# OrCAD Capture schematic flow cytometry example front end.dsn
size B
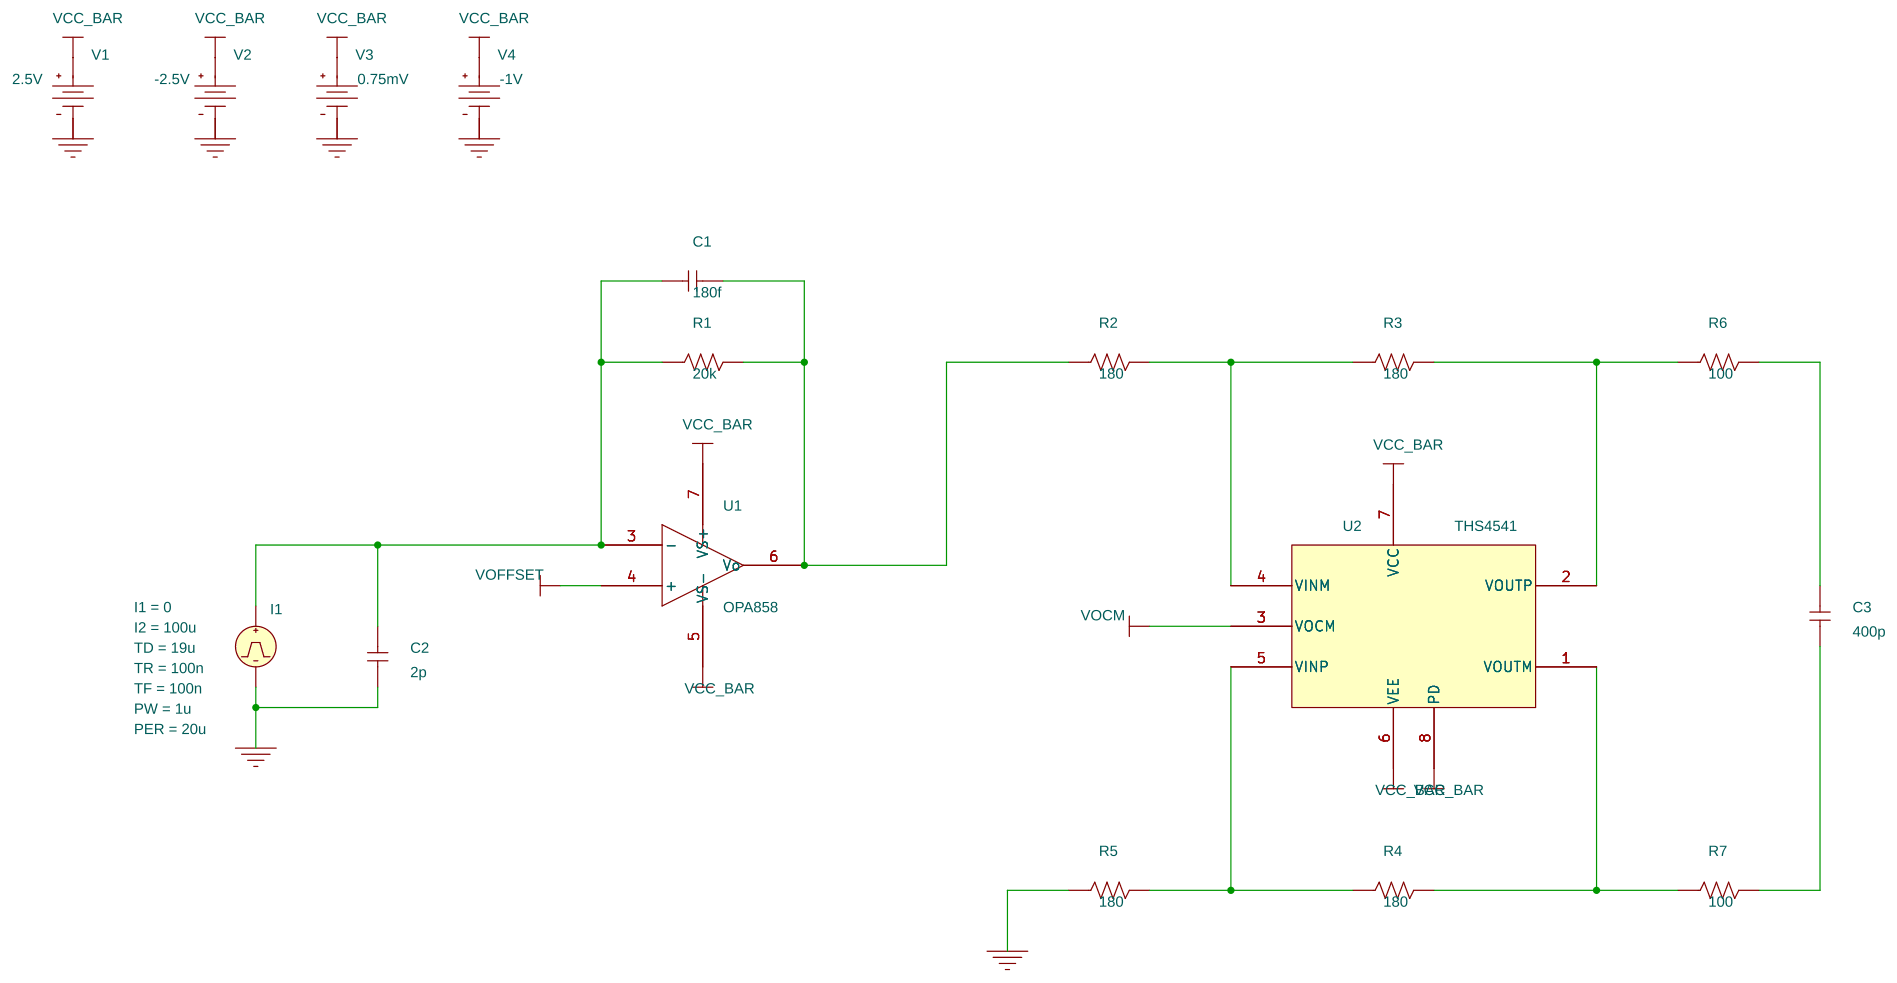
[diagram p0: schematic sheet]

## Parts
C1  180f  [cap196]
C2  2p  [cap196]
C3  400p  [cap196]
I1  IPULSE
R1  20k  [AXRC05]
R2  180  [AXRC05]
R3  180  [AXRC05]
R4  180  [AXRC05]
R5  180  [AXRC05]
R6  100  [AXRC05]
R7  100  [AXRC05]
U1  OPA858
U2  THS4541
V1  VDC
V2  VDC
V3  VDC
V4  VDC

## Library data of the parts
C1-C3 = C
I1 = IPULSE: AC: 1Aac; I1: 0; I2: 100u; PER: 20u; PW: 1u; TD: 19u; TF: 100n; TR: 100n
R1-R7 = R
U1 = OPA858: Testbenches: [{"TestbenchDisplayName": "OPA858 PSPICE Model", "TestbenchURL": "https://software-dl.ti.com/pspice/esd/models/OPA858_V3.0.zip", "TestbenchOpj": "OPA858"}]; Version: 3; productURL: http://www.ti.com/document-viewer/OPA858/datasheet/
U2 = THS4541: Testbenches: [{"TestbenchDisplayName": "THS4541 Simulation Model", "TestbenchURL": "https://software-dl.ti.com/pspice/esd/models/THS4541_V1.0.zip", "TestbenchOpj": "THS4541.OPJ"}]; Version: 1; productURL: http://www.ti.com/document-viewer/THS4541/datasheet/
V1 = VDC: DC: 2.5V
V2 = VDC: DC: -2.5V
V3 = VDC: DC: 0.75mV
V4 = VDC: DC: -1V

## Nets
VCC: U1.7(VS+) U2.7(VCC) U2.8(PD) V1.0(+)
VEE: U1.5(VS-) U2.6(VEE) V2.0(+)
0: C2.1 I1.2(-) R5.1 V1.1(-) V2.1(-) V3.1(-) V4.1(-)
Vocm: U2.3(VOCM) V3.0(+)
Voffset: U1.4(+) V4.0(+)
N00797: C1.1 C2.2 I1.1(+) R1.1 U1.3(-)
N00804: C1.2 R1.2 R2.1 U1.6(Vo)
N00833: R4.1 R5.2 U2.5(VINP)
N00847: R2.2 R3.1 U2.4(VINM)
N00861: R3.2 R6.1 U2.2(VOUTP)
N00868: R4.2 R7.1 U2.1(VOUTM)
N00917: C3.1 R7.2
N00924: C3.2 R6.2
